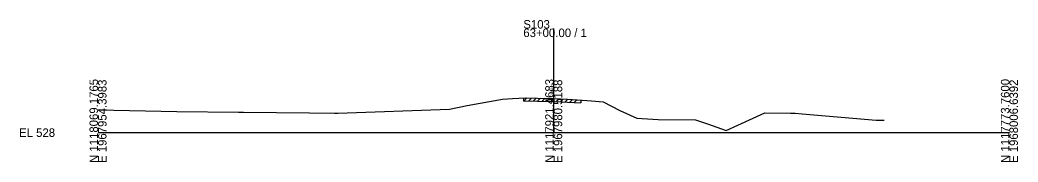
# Model space of a CAD drawing. Extents: x 974 to 1303, y 990 to 14518.
# Drawn here: x 974.3 to 1302.8, y 7490.3 to 7537.1 of the extents above; entities that cross this region are included whole.
import ezdxf

# ---------------------------------------------------------------- set-up
doc = ezdxf.new("R2010")
doc.units = 0
for name, color, linetype in [('Level 10', 7, 'Continuous'), ('Level 60', 7, 'Continuous'), ('Level 61', 7, 'Continuous'), ('Level 63', 7, 'Continuous')]:
    doc.layers.add(name, color=color, linetype=linetype)

msp = doc.modelspace()

# ---------------------------------------------------------------- linework, layer by layer
at = {"layer": 'Level 60'}
for p, q in [((1121.48, 7508.95), (1133.19, 7511.06)), ((1133.19, 7511.06), (1136.4, 7511.24)), ((1136.4, 7511.24), (1140.63, 7511.43)), ((1140.63, 7511.43), (1144.71, 7511.36)), ((1144.71, 7511.36), (1148.78, 7511.28)), ((1148.78, 7511.28), (1150, 7511.22)), ((1150, 7511.22), (1154.57, 7511)), ((1154.57, 7511), (1159.32, 7510.75)), ((1159.32, 7510.75), (1162.4, 7510.48)), ((1162.4, 7510.48), (1166.28, 7510.11)), ((1000, 7507.5), (1025.94, 7507)), ((1025.94, 7507), (1046.28, 7506.79)), ((1078.99, 7506.42), (1115.66, 7507.72)), ((1115.66, 7507.72), (1121.48, 7508.95)), ((1166.28, 7510.11), (1171.71, 7507.33)), ((1171.71, 7507.33), (1177.32, 7504.74)), ((1046.28, 7506.79), (1047.91, 7506.77)), ((1047.91, 7506.77), (1069.59, 7506.49)), ((1069.59, 7506.49), (1077.85, 7506.39)), ((1077.85, 7506.39), (1078.99, 7506.42)), ((1177.32, 7504.74), (1184.4, 7504.35)), ((1184.4, 7504.35), (1196.65, 7504.19)), ((1196.65, 7504.19), (1200.59, 7502.86)), ((1210.57, 7502.47), (1219.51, 7506.56)), ((1219.51, 7506.56), (1227.93, 7506.47)), ((1227.93, 7506.47), (1229.43, 7506.43)), ((1229.43, 7506.43), (1231.78, 7506.23)), ((1231.78, 7506.23), (1256.13, 7504.11)), ((1256.13, 7504.11), (1257.25, 7504.14)), ((1257.25, 7504.14), (1258.82, 7504.15)), ((1200.59, 7502.86), (1206.81, 7500.69)), ((1206.81, 7500.69), (1210.57, 7502.47))]:
    msp.add_line(p, q, dxfattribs=at)
at = {"layer": 'Level 61'}
for p, q in [((1140.19, 7510.41), (1141.2, 7511.42)), ((1140.19, 7510.41), (1140.19, 7511.41)), ((1140.19, 7510.41), (1140.63, 7510.43)), ((1140.63, 7510.43), (1144.71, 7510.36)), ((1141.69, 7510.41), (1142.67, 7511.39)), ((1143.19, 7510.38), (1144.17, 7511.37)), ((1144.69, 7510.36), (1145.67, 7511.34)), ((1144.71, 7510.36), (1148.78, 7510.28)), ((1146.19, 7510.33), (1147.17, 7511.31)), ((1147.69, 7510.3), (1148.67, 7511.28)), ((1148.78, 7510.28), (1150, 7510.22)), ((1149.19, 7510.26), (1150.15, 7511.21)), ((1150.69, 7510.19), (1151.65, 7511.14)), ((1152.19, 7510.12), (1153.15, 7511.07)), ((1153.69, 7510.05), (1154.65, 7511)), ((1155.19, 7509.97), (1156.14, 7510.92)), ((1156.69, 7509.89), (1157.64, 7510.84)), ((1158.9, 7510.77), (1158.9, 7509.77)), ((1150, 7510.22), (1154.57, 7510)), ((1154.57, 7510), (1158.9, 7509.77))]:
    msp.add_line(p, q, dxfattribs=at)
at = {"layer": 'Level 63'}
for p, q in [((1150, 7500), (1150, 7534.29)), ((1000, 7500), (1150, 7500)), ((1150, 7500), (1300, 7500))]:
    msp.add_line(p, q, dxfattribs=at)

# ---------------------------------------------------------------- texts
at = {"layer": 'Level 10'}
msp.add_text('539.22', height=0.9, rotation=90, dxfattribs=at).set_placement((1149.95, 7511.72))
at = {"layer": 'Level 63'}
for s, p in [('S103', (1140, 7534.29)), ('63+00.00 / 1', (1140, 7531.49)), ('EL 528', (974, 7498.6))]:
    msp.add_text(s, height=2.8, dxfattribs=at).set_placement(p)
for s, p in [('N 1118069.1765', (1000, 7490)), ('E 1967954.3983', (1002.8, 7490)), ('N 1117921.4683', (1150, 7490)), ('E 1967980.5188', (1152.8, 7490)), ('N 1117773.7600', (1300, 7490)), ('E 1968006.6392', (1302.8, 7490))]:
    msp.add_text(s, height=2.8, rotation=90, dxfattribs=at).set_placement(p)

doc.saveas('drawing.dxf')
